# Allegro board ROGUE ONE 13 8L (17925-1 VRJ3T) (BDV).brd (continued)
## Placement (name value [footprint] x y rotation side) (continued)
C7201  SC2D2U10V3KX-1DLGP-U  [C603H36]  18.23 33.55 270 top
C7202  SC2D2U10V3KX-1DLGP-U  [C603H36]  14.92 29.05 180 top
C7203  SC2D2U10V3KX-1DLGP-U  [C603H36]  18.2 37 270 top
C7204  SC22U6D3V3MX-L1-GP  [C603H40]  7.38 32.15 270 top
C7205  SC22U6D3V3MX-1-DL-GP  [C603H40]  7.38 33.42 270 top
C7206  SCD1U16V2KX-3DLGP  [C402H22]  7.38 32.15 90 bottom
C7208  SC10U6D3V3MX-DL-GP  [C603H36]  16.22 29.05 0 top
C7210  SC1U10V2KX-1DLGP  [C402H22]  14.03 36.21 0 bottom
C7211  SC10U6D3V3MX-DL-GP  [C603H36]  18.2 35.73 90 top
C7212  SCD22U10V2KX-2-GP  [C402H22]  11.57 37.74 180 bottom
C7217  SC220P50V2KX-3DLGP  [C402H22]  9.36 42.33 180 top
C7218  SC220P50V2KX-3DLGP  [C402H22]  7.99 42.36 180 top
C7244  SCD1U16V2KX-3DLGP  [C402H22]  16.3 21.61 90 bottom
C7301  SC1U25V3KX-1-DLGP  [C603H36]  6.97 39.36 180 top
C7302  SCD1U25V2KX-1-DL-GP  [C402H22]  7.02 59.84 90 bottom
C7303  SCD1U25V2KX-1-DL-GP  [C402H22]  11.7 60.34 180 top
C7304  SCD1U25V2KX-1-DL-GP  [C402H22]  7.02 60.6 90 bottom
C7305  SC4D7U25V5KX-DL-GP  [C805H54]  10.71 60.19 270 bottom
C7306  SC1U25V3KX-1-DLGP  [C603H36]  9.56 57.68 0 top
C7307  SCD1U25V2KX-1-DL-GP  [C402H22]  10.58 57.55 0 top
C7401  SC1500P50V2KX-2-DL-GP  [C402H22]  20.21 59.33 90 bottom
C9106  SC10U6D3V3MX-DL-GP  [C603H36]  187.49 47.01 90 top
C9108  SCD1U16V2KX-3DLGP  [C402H22]  185.84 45.74 0 top
C9109  SC10U6D3V3MX-DL-GP  [C603H36]  176.57 46.63 270 top
C9112  SCD1U16V2KX-3DLGP  [C402H22]  183.81 52.72 90 top
C9113  SCD1U16V2KX-3DLGP  [C402H22]  177.05 47.87 270 top
C9201  SC1U10V2KX-1DLGP  [C402H22]  181.52 88.16 90 bottom
CN6601  STAR-CON40-8-GP  [300E40-1010RA-G3]  170.3 37.55 180 bottom
CPU1  WHISKEY-LAKE-GP  [BGA1528M2446-1H52]  116.72 76.86 270 bottom
D1701  RB520S30-GP  [SOD523AKH26]  125.52 49.17 90 bottom
D2401  RB751V-40H-GP  [SOD323AKH38]  20.99 23.64 90 bottom
D2402  L1SS355T1G-GP  [SOD323AKH44]  32.2 25.47 90 top
D2403  RB520S30-GP  [SOD523AKH26]  43.68 27.2 270 bottom
D2404  RB751V-40H-GP  [SOD323AKH38]  31.03 12.85 180 top
D2501  BAT54C-12-GP  [SOT-23-9H44]  193.33 40.02 0 bottom
D2502  RB751VM-40TE-17-GP  [SOD323-2513AKH36]  186.86 61.99 270 top
D2503  BAT54A-11-GP  [SOT-23-9H44]  158.28 68.73 270 bottom
D2601  RB551V30-GP  [SOD323AKH38]  187.36 70.12 270 bottom
D2702  BAT54C-12-GP  [SOT-23-9H44]  180.46 11.96 180 bottom
D4001  L1SS355T1G-GP  [SOD323AKH44]  92.7 9.04 270 bottom
D4002  RB520S30-GP  [SOD523AKH26]  17.69 18.43 90 top
D4003  RB520S30-GP  [SOD523AKH26]  14.9 18.56 180 bottom
D4301  P6AF24A-R1-00001-GP  [D4724AKH44]  46.7 92.12 180 bottom
D4302  LBAV99LT1G-1-GP  [SOT23-2D4-312H44]  34.2 31.9 180 top
D4303  L30ESD24VC3-2-GP  [SOT23-2D4-312H60]  47.54 98.7 180 bottom
D4304  SMF18A-GP  [SOD123AK-2H43]  98.72 8.78 270 bottom
D4305  RB751V-40-2-GP  [SOD323AKH38]  19.72 44.85 0 top
D5501  BAT54C-12-GP  [SOT-23-9H44]  77.13 99.33 180 bottom
D5502  BAT54C-12-GP  [SOT-23-9H44]  73.7 99.46 180 bottom
D5701  LBAW56LT1G-GP  [SOT23-2D4-312H44]  21.22 95.37 0 top
D6101  RB520S30-GP  [SOD523AKH26]  168.19 51.71 90 top
D6102  RB520S30-GP  [SOD523AKH26]  167.43 46.88 90 top
D6401  BAT54A-11-GP  [SOT-23-9H44]  175.81 4.97 270 bottom
D7301  BX310F-R1-00000-GP  [D4724AKH44]  12.87 57.8 90 bottom
DB1  DM-ACES-CON14-5-GP-01  [DM-87212-1400N-01]  36.49 21.35 90 top
DB3  ACES-CON6-58-GP  [50696-00601-001]  34.84 2.3 0 top
DCIN1  ETY-CON8-23-GP-U  [3703K-Q08N-03R-U]  39.7 94.3 0 bottom
EC1706  SC1KP50V2KX-1DLGP  [C402H22]  146.42 83.13 180 bottom
EC1707  SCD1U16V2KX-3DLGP  [C402H22]  136.18 48 90 bottom
EC1712  SCD1U16V2KX-3DLGP  [C402H22]  132.25 48.81 270 bottom
EC1801  SC10P50V2JN-4DLGP  [C402H22]  130.49 56.84 90 top
EC1803  SC4D7P50V2BN-2-GP  [C402H22]  125.44 57.52 270 bottom
EC1804  SCD1U16V2KX-3DLGP  [C402H22]  135.8 26.18 0 bottom
EC1901  SC10P50V2JN-4DLGP  [C402H22]  169.84 22.7 270 bottom
EC1903  SC33P50V2JN-3DLGP  [C402H22]  173.67 24.43 0 bottom
EC2201  SCD1U25V2KX-1-DL-GP  [C402H22]  127.22 81.35 270 top
EC2402  SCD1U25V2KX-1-DL-GP  [C402H22]  23.56 17.54 0 top
EC2403  SCD1U25V2KX-1-DL-GP  [C402H22]  43.22 23.51 180 bottom
EC2501  SC4D7P50V2BN-2-GP  [C402H22]  137.63 54.6 180 bottom
EC2502  SC4D7P50V2BN-2-GP  [C402H22]  153.1 55.54 180 bottom
EC2503  SC10P50V2JN-4DLGP  [C402H22]  139.97 56.69 90 bottom
EC2601  SC10P50V2JN-4DLGP  [C402H22]  184.32 68.85 90 bottom
EC2602  SC10P50V2JN-4DLGP  [C402H22]  185.84 68.85 270 bottom
EC2709  SCD01U50V2KX-1DLGP  [C402H22]  183.3 14.88 270 bottom
EC2710  SCD01U50V2KX-1DLGP  [C402H22]  183.25 20.11 270 bottom
EC2711  SCD01U50V2KX-1DLGP  [C402H22]  183.43 24.78 90 top
EC2712  SCD1U25V2KX-1-DL-GP  [C402H22]  183.43 24.78 270 bottom
EC2713  SCD1U25V2KX-1-DL-GP  [C402H22]  177.71 16.78 180 top
EC2714  SCD1U25V2KX-1-DL-GP  [C402H22]  183.3 14.88 90 top
EC2901  SC1KP50V2KX-1DLGP  [C402H22]  13.25 3.7 0 top
EC2902  SC1KP50V2KX-1DLGP  [C402H22]  15.03 4.97 90 top
EC2903  SC1KP50V2KX-1DLGP  [C402H22]  16.68 4.97 270 top
EC2904  SC1KP50V2KX-1DLGP  [C402H22]  18.84 4.34 0 top
EC4301  SC10U25V5KX-DL-GP  [C805H58]  39.76 88.33 90 bottom
EC4302  SCD1U25V2KX-1-DL-GP  [C402H22]  39.79 89.3 270 top
EC4306  SC10P50V2JN-4DLGP  [C402H22]  117.01 18.31 90 top
EC4307  SC1KP50V2KX-1DLGP  [C402H22]  102.27 13.1 0 bottom
EC4308  SCD1U25V2KX-1-DL-GP  [C402H22]  101.77 8.02 180 bottom
EC4309  SC10P50V2JN-4DLGP  [C402H22]  115.1 20.08 90 top
EC4310  SC10P50V2JN-4DLGP  [C402H22]  113.58 20.08 270 top
EC4311  SCD1U25V2KX-1-DL-GP  [C402H22]  46.52 95.4 270 bottom
EC4312  SC1KP50V2KX-1DLGP  [C402H22]  39.79 88.54 270 top
EC4313  SCD1U25V2KX-1-DL-GP  [C402H22]  39.79 87.78 270 top
EC4534  SC2D2U25V5KX-2-GP  [C805H54]  99.15 24.94 0 bottom
EC4701  SCD1U25V2KX-1-DL-GP  [C402H22]  96.05 70.38 90 top
EC5001  SCD1U25V2KX-1-DL-GP  [C402H22]  122.92 74.44 270 top
EC5501  SC8P50V2DN-1DL-GP  [C402H22]  100.12 99.84 90 top
EC5503  SC33P50V2JN-3DLGP  [C402H22]  110.15 101.11 90 top
EC5504  SC33P50V2JN-3DLGP  [C402H22]  108.62 101.11 270 top
EC5505  SCD1U25V2KX-1-DL-GP  [C402H22]  144.95 100.86 180 top
EC5506  SC33P50V2JN-3DLGP  [C402H22]  121.07 98.44 270 top
EC6501  SC33P50V2JN-3DLGP  [C402H22]  89.96 10.56 90 top
EC6502  SC33P50V2JN-3DLGP  [C402H22]  88.43 10.56 270 top
EC6503  SC33P50V2JN-3DLGP  [C402H22]  89.68 12.11 0 bottom
EC6504  SC33P50V2JN-3DLGP  [C402H22]  84.72 13.07 90 bottom
EC8901  SCD1U25V2KX-1-DL-GP  [C402H22]  125.26 97.3 180 top
EC8902  SCD1U25V2KX-1-DL-GP  [C402H22]  77.64 92.47 180 top
EC8903  SCD1U25V2KX-1-DL-GP  [C402H22]  96.91 96.87 270 top
EC8904  SCD1U25V2KX-1-DL-GP  [C402H22]  105.02 97.45 180 top
EC8905  SC1U10V2KX-1DLGP  [C402H22]  99.48 84.09 180 top
EC8906  SCD1U25V2KX-1-DL-GP  [C402H22]  103.04 80.54 0 top
EC8907  SCD1U25V2KX-1-DL-GP  [C402H22]  143.8 98.44 180 top
EC8908  SCD1U25V2KX-1-DL-GP  [C402H22]  52.11 66.19 270 top
EC8909  SCD1U25V2KX-1-DL-GP  [C402H22]  55.92 84.85 270 top
EC8910  SCD1U25V2KX-1-DL-GP  [C402H22]  39.54 35.83 270 top
EC8911  SCD1U25V2KX-1-DL-GP  [C402H22]  50.59 23.13 0 top
EC8912  SCD1U25V2KX-1-DL-GP  [C402H22]  71.13 22.34 0 top
EC8913  SCD1U25V2KX-1-DL-GP  [C402H22]  61.76 64.15 90 top
EC8914  SCD1U25V2KX-1-DL-GP  [C402H22]  107.23 25.16 0 top
EC8915  SCD1U25V2KX-1-DL-GP  [C402H22]  153.33 27.96 180 top
EC8916  SCD1U25V2KX-1-DL-GP  [C402H22]  164 36.98 270 top
EC8917  SCD1U25V2KX-1-DL-GP  [C402H22]  55.79 80.41 270 top
EC8918  SCD1U25V2KX-1-DL-GP  [C402H22]  171.62 98.87 180 top
EC8919  SCD1U25V2KX-1-DL-GP  [C402H22]  168.42 43.93 180 top
EC8920  SCD1U25V2KX-1-DL-GP  [C402H22]  124.98 4.67 0 top
EC8921  SCD1U25V2KX-1-DL-GP  [C402H22]  176.82 68.52 180 top
EC8922  SCD1U25V2KX-1-DL-GP  [C402H22]  79.67 8.27 180 top
EC8923  SCD1U25V2KX-1-DL-GP  [C402H22]  124.83 11.52 180 top
EC8924  SCD1U25V2KX-1-DL-GP  [C402H22]  116.24 23.51 90 top
EC8925  SCD1U25V2KX-1-DL-GP  [C402H22]  75.22 13.73 90 top
EC8926  SCD1U25V2KX-1-DL-GP  [C402H22]  174.18 2.1 270 bottom
EC8927  SCD1U25V2KX-1-DL-GP  [C402H22]  7.71 4.41 0 top
EC8928  SCD1U25V2KX-1-DL-GP  [C402H22]  5.25 31.39 180 top
EC8929  SCD1U25V2KX-1-DL-GP  [C402H22]  66.08 12.08 270 top
EC8930  SCD1U25V2KX-1-DL-GP  [C402H22]  65.67 50.23 270 top
EC8931  SCD1U25V2KX-1-DL-GP  [C402H22]  113.96 52.34 270 top
EC8932  SCD1U25V2KX-1-DL-GP  [C402H22]  113.96 56.41 270 top
EC8933  SCD1U25V2KX-1-DL-GP  [C402H22]  124.12 51.07 90 top
EC8934  SCD1U25V2KX-1-DL-GP  [C402H22]  123.23 54.93 90 top
EC8937  SCD1U25V2KX-1-DL-GP  [C402H22]  75.91 77.23 0 top
EC8938  SCD1U25V2KX-1-DL-GP  [C402H22]  73.19 88.66 270 top
EC8939  SCD1U25V2KX-1-DL-GP  [C402H22]  66.82 52.9 180 top
EC8940  SCD1U25V2KX-1-DL-GP  [C402H22]  89.55 49.45 180 top
EC8941  SCD1U25V2KX-1-DL-GP  [C402H22]  86.96 52.39 180 top
EC8942  SCD1U25V2KX-1-DL-GP  [C402H22]  112.82 48.91 270 top
EC8943  SCD1U25V2KX-1-DL-GP  [C402H22]  166.54 70.25 90 top
EC8944  SCD1U25V2KX-1-DL-GP  [C402H22]  168.44 103.9 270 top
EC8945  SCD1U25V2KX-1-DL-GP  [C402H22]  56.3 89.68 270 top
EC8946  SCD1U25V2KX-1-DL-GP  [C402H22]  79.8 24.53 180 bottom
EC8947  SCD1U25V2KX-1-DL-GP  [C402H22]  45.91 53.99 0 bottom
EC8948  SCD1U25V2KX-1-DL-GP  [C402H22]  47.79 38.37 270 bottom
EC8949  SCD1U25V2KX-1-DL-GP  [C402H22]  62.78 25.09 180 bottom
EC8950  SCD1U25V2KX-1-DL-GP  [C402H22]  58.36 24.99 180 bottom
ED301  AZ5125-02S-R7G-GP  [SOT23-2D4-312H46]  117.21 95.24 180 bottom
ED1701  AZ5125-02S-R7G-GP  [SOT23-2D4-312H46]  139.71 54.76 90 top
ED1702  AZ5125-02S-R7G-GP  [SOT23-2D4-312H46]  156.99 87.67 0 top
ED1703  AZ5125-02S-R7G-GP  [SOT23-2D4-312H46]  16.55 14.83 180 bottom
ED1704  AZ5125-02S-R7G-GP  [SOT23-2D4-312H46]  56.22 78.83 90 bottom
ED1801  AZ5125-02S-R7G-GP  [SOT23-2D4-312H46]  138.65 47.82 0 bottom
ED2403  AZ5125-02S-R7G-GP  [SOT23-2D4-312H46]  24.68 38.5 90 bottom
ED4304  LBAV99LT1G-1-GP  [SOT23-2D4-312H44]  36.49 34.44 0 bottom
ED4305  LBAV99LT1G-1-GP  [SOT23-2D4-312H44]  26.84 31.01 0 top
ED4306  LBAV99LT1G-1-GP  [SOT23-2D4-312H44]  30.27 30.37 0 top
ED5501  AZC099-04S-2-GP  [SOT-6H58]  116.88 99.03 180 bottom
ED5502  AZ5125-02S-R7G-GP  [SOT23-2D4-312H46]  136.54 99.15 270 bottom
ED5701  AZ1043-04F-R7G-GP  [DFN10G2510H22]  15.15 84.73 270 top
ED5702  AZ1043-04F-R7G-GP  [DFN10G2510H22]  15.15 88.16 90 top
ED5703  AZ1043-04F-R7G-GP  [DFN10G2510H22]  15.15 91.2 270 top
ED6301  L05ESDL5V0NA-4-GP  [SLP2510P8-1H22]  185.38 11.68 90 bottom
ED6302  L05ESDL5V0NA-4-GP  [SLP2510P8-1H22]  153.61 14.37 270 top
ED6401  AZ5125-02S-R7G-GP  [SOT23-2D4-312H46]  17.44 100.22 90 top
ED7301  L05ESDL5V0NA-4-GP  [SLP2510P8-1H22]  13.7 70.12 90 top
ED7302  L05ESDL5V0NA-4-GP  [SLP2510P8-1H22]  13.88 66.95 90 top
ED7303  L05ESDL5V0NA-4-GP  [SLP2510P8-1H22]  12.1 65.96 180 bottom
ED7305  AZ5315-02F-GP  [SOT883-1D0-321H20]  14.95 63.54 0 bottom
ED7306  AZ5315-02F-GP  [SOT883-1D0-321H20]  10.58 71.39 180 bottom
ED9202  AZ5315-02F-GP  [SOT883-1D0-321H20]  181.57 85.26 0 bottom
EL4301  0R0805-PAD-2-GP-U  [0R0805-PAD-1-U]  44.24 87.8 180 bottom
EL4302  0R0805-PAD-2-GP-U  [0R0805-PAD-1-U]  42.33 87.8 180 bottom
EL4303  0R0805-PAD-2-GP-U  [0R0805-PAD-1-U]  35.98 88.33 90 bottom
EL4304  0R0805-PAD-2-GP-U  [0R0805-PAD-1-U]  35.98 86.51 90 bottom
EL5501  DLM0NSN900HY2D-GP  [LD85D65-4P-1H20]  117.9 102 180 bottom
EL7201  DLM0NSN900HY2D-GP  [LD85D65-4P-1H20]  12.87 64.05 0 bottom
EL7202  DLM0NSN900HY2D-GP  [LD85D65-4P-1H20]  11.32 64.05 0 bottom
ER2901  0R0603-PAD-2-GP-U  [0R0603-PAD-1-U]  16.68 6.75 0 top
ER2902  0R0603-PAD-2-GP-U  [0R0603-PAD-1-U]  18.2 6.75 0 top
ER2903  0R0603-PAD-2-GP-U  [0R0603-PAD-1-U]  13.25 5.73 0 top
ER2904  0R0603-PAD-2-GP-U  [0R0603-PAD-1-U]  15.41 6.75 0 top
ER7301  0R5J-5-GP  [R805H24]  7.15 57.68 0 bottom
ER7302  0R5J-5-GP  [R805H24]  9.06 57.68 0 bottom
F5501  POLYSW-1D1A6V-9-GP-U  [POLYSW-2114H30]  137.3 100.65 0 top
F5502  POLYSW-1D1A6V-9-GP-U  [POLYSW-2114H30]  104.81 101.24 270 top
F5503  POLYSW-1D1A24V-GP-U  [POLYSW-4633-UH43]  75.73 95.65 90 bottom
F5504  POLYSW-1D1A6V-9-GP-U  [POLYSW-2114H30]  122.09 101.62 0 top
F5701  POLYSW-1D1A6V-9-GP-U  [POLYSW-2114H30]  17.82 95.14 270 top
F6501  POLYSW-1D1A6V-9-GP-U  [POLYSW-2114H30]  72.05 16.4 180 bottom
FAN1  ACES-CON4-29-GP  [50224-0040N-001]  186.8 76.6 270 bottom
FC1102  SC2D2U6D3V2MX-DL-GP  [C402H22]  123.23 54.12 90 top
FC1103  SC18P50V2JN-1DLGP  [C402H22]  113.58 69.49 180 top
FC1801  SC4D7P50V2BN-2-GP  [C402H22]  125.44 56.74 270 bottom
FC2738  SC12P50V2JN-DL-GP  [C402H22]  167.6 18.48 270 bottom
FC5501  SC18P50V2JN-1DLGP  [C402H22]  100.5 97.17 270 top
FC5502  SC18P50V2JN-1DLGP  [C402H22]  104.56 98.57 90 top
FC5505  SC18P50V2JN-1DLGP  [C402H22]  80.05 104.29 90 bottom
FC5701  SC12P50V2JN-DL-GP  [C402H22]  34.08 87.57 0 bottom
FC5702  SC12P50V2JN-DL-GP  [C402H22]  31.81 75.13 90 bottom
FC5703  SC12P50V2JN-DL-GP  [C402H22]  26.28 75.84 180 bottom
FC5704  SC12P50V2JN-DL-GP  [C402H22]  24.3 77.34 180 bottom
FC6101  SC10P50V2JN-4DLGP  [C402H22]  166.54 63.39 0 top
FC8905  SC4D7P50V2BN-2-GP  [C402H22]  154.09 27.96 180 top
FC8906  SC4D7P50V2BN-2-GP  [C402H22]  164 37.74 270 top
FC8907  SC4D7P50V2BN-2-GP  [C402H22]  166.16 60.98 90 top
FC8908  SC4D7P50V2BN-2-GP  [C402H22]  166.28 75.46 90 top
FC8909  SC4D7P50V2BN-2-GP  [C402H22]  174.66 97.94 270 top
FC8910  SC4D7P50V2BN-2-GP  [C402H22]  41.75 49.19 270 top
FC8911  SC18P50V2JN-1DLGP  [C402H22]  47.79 39.13 270 bottom
FC8912  SC4D7P50V2BN-2-GP  [C402H22]  100.5 24.4 0 bottom
FC8913  SC18P50V2JN-1DLGP  [C402H22]  170.98 104.41 0 bottom
FC8914  SC4D7P50V2BN-2-GP  [C402H22]  58.71 93.62 180 top
FC8915  SC4D7P50V2BN-2-GP  [C402H22]  61 79.39 90 top
FC8916  SC4D7P50V2BN-2-GP  [C402H22]  62.4 67.28 90 top
FC8917  SC4D7P50V2BN-2-GP  [C402H22]  49.82 63.9 270 top
FC8918  SC4D7P50V2BN-2-GP  [C402H22]  52.36 59.45 90 top
FC8919  SC4D7P50V2BN-2-GP  [C402H22]  43.6 37.1 90 top
FC8920  SC4D7P50V2BN-2-GP  [C402H22]  45.38 28.85 180 top
FC8921  SC4D7P50V2BN-2-GP  [C402H22]  54.14 22.88 0 top
FC8922  SC4D7P50V2BN-2-GP  [C402H22]  72.94 22.88 0 top
FC8923  SC4D7P50V2BN-2-GP  [C402H22]  92.11 22.17 0 top
FC8924  SC4D7P50V2BN-2-GP  [C402H22]  117.26 25.04 0 top
FC8925  SC4D7P50V2BN-2-GP  [C402H22]  6.39 31.13 270 top
FC8926  SC4D7P50V2BN-2-GP  [C402H22]  64.94 3.07 270 top
FC8927  SC4D7P50V2BN-2-GP  [C402H22]  66.82 19.42 270 top
FC8928  SC4D7P50V2BN-2-GP  [C402H22]  125.74 4.67 0 top
FC8929  SC4D7P50V2BN-2-GP  [C402H22]  8.68 15 90 bottom
FC8930  SC4D7P50V2BN-2-GP  [C402H22]  34.35 76.88 270 bottom
FC8931  SC4D7P50V2BN-2-GP  [C402H22]  10.07 13.86 180 bottom
FC8932  SC18P50V2JN-1DLGP  [C402H22]  57.32 89.17 0 bottom
FC8933  SC4D7P50V2BN-2-GP  [C402H22]  154.85 69.87 270 bottom
FC8934  SC18P50V2JN-1DLGP  [C402H22]  170.3 99.21 90 bottom
FC8935  SC4D7P50V2BN-2-GP  [C402H22]  73.57 20.97 180 top
FC8936  SC4D7P50V2BN-2-GP  [C402H22]  80.68 7.64 180 top
FC8937  SC4D7P50V2BN-2-GP  [C402H22]  116.24 22.75 90 top
FC8938  SC4D7P50V2BN-2-GP  [C402H22]  125.59 11.52 180 top
FC8939  SC4D7P50V2BN-2-GP  [C402H22]  115.99 21.99 90 top
FC8940  SC4D7P50V2BN-2-GP  [C402H22]  48.93 61.74 90 bottom
FC8941  SC4D7P50V2BN-2-GP  [C402H22]  38.34 10.84 90 top
FC8942  SC4D7P50V2BN-2-GP  [C402H22]  134.41 5.83 90 top
FC8943  SC18P50V2JN-1DLGP  [C402H22]  145.91 71.49 270 bottom
FC8944  SC4D7P50V2BN-2-GP  [C402H22]  17.26 29.15 0 top
FC8945  SC18P50V2JN-1DLGP  [C402H22]  158.03 94.38 0 bottom
FC8946  SC18P50V2JN-1DLGP  [C402H22]  65.83 46.5 0 bottom
FC8947  SC4D7P50V2BN-2-GP  [C402H22]  72.3 46.5 0 bottom
FC8948  SC18P50V2JN-1DLGP  [C402H22]  113.45 46.37 0 bottom
FC8949  SC18P50V2JN-1DLGP  [C402H22]  142.91 46.5 0 bottom
FC8950  SC4D7P50V2BN-2-GP  [C402H22]  102.78 32.28 180 bottom
FC8951  SC18P50V2JN-1DLGP  [C402H22]  55.28 28.21 180 bottom
FC8952  SC18P50V2JN-1DLGP  [C402H22]  90.59 28.09 180 bottom
FC8953  SC18P50V2JN-1DLGP  [C402H22]  108.5 28.47 180 bottom
FC8954  SC18P50V2JN-1DLGP  [C402H22]  136.06 28.47 180 bottom
FP1  PTWO-CON8-11-GP  [FH52-8S-D5SH]  185.9 85 270 bottom
FSW1  SW-SLIDE3P-11-GP  [MSS3-Q-T-R]  193.46 29.86 90 top
G1801  GAP-OPEN  [CON2O-U]  145.84 25.42 90 bottom
G5701  GAP-CLOSE-PWR-3-GP  [GAP-CLOSE-PWR-3]  35.24 79.88 90 bottom
H1  HOLE335R178-GP  [HOLE335R178]  28.2 99.1 0 bottom
H2  HOLE335R178-GP  [HOLE335R178]  27.2 4.75 0 bottom
H3  HOLE296R182-GP  [HOLE296R182]  182.05 4 0 bottom
H4  HOLE394X394R174-GP  [HOLE394X394R174]  31.2 66.3 0 bottom
H5  HOLE296R182-GP  [HOLE296R182]  150.2 102.46 0 bottom
H6  HOLE276R150-GP  [HOLE276R150]  84.49 89.96 180 bottom
H7  HOLE276R150-GP  [HOLE276R150]  84.49 65.66 180 bottom
H8  HOLE276R150-GP  [HOLE276R150]  145.49 65.66 180 bottom
H9  HOLE276R150-GP  [HOLE276R150]  145.49 89.96 180 bottom
H10  HOLE335R178-GP  [HOLE335R178]  151.2 45.3 0 bottom
H12  STF237R113H62-10-GP  [STF237R113H62]  13.7 76.3 0 bottom
H13  HOLE315R197-GP  [HOLE315R197]  132.42 12.9 0 bottom
HDMI1  SKT-HDMI23-169-GP  [SKT-HDMI23-188142]  3.72 88.52 90 bottom
KB1  ACES-CON30-28-GP  [196528-30041-3]  47.7 8.6 180 bottom
KBBL1  ACES-CON4-90-GP-U  [50698-00401-W01-U]  69.7 6.3 180 bottom
LCD1  STAR-CON50-2-GP-U  [300E50-1030RA-G4]  98.4 99.8 0 bottom
LED1  LED-YW-5-GP  [LED3020-3P-19H44]  3 100.95 0 top
NOREF  -  []  94.41 66.65 90 top
NOREF#2  -  []  142.31 135 0 top
NOREF#3  -  []  7.12 66.59 90 top
NOREF#4  -  []  132.42 19.25 0 top
NOREF#5  -  []  7.12 73.79 0 top
NOREF#6  -  []  6.57 67.39 0 top
NOREF#7  -  [unnamed#2]  197.36 62.3 0 top
NOREF#8  -  []  7.12 73.79 0 top
NOREF#9  -  []  6.57 69.79 0 top
NOREF#10  -  []  108.52 65.55 90 top
NOREF#11  -  []  34.44 100.24 90 top
NOREF#12  -  []  7.78 72.94 90 top
NOREF#13  -  []  142.31 96.9 90 top
NOREF#14  -  [unnamed#2]  178.7 103.35 0 top
NOREF#15  -  []  7.12 73.79 0 top
NOREF#16  -  []  190.85 31.86 90 top
NOREF#17  -  []  7.12 73.79 90 top
NOREF#18  -  []  97.67 63.86 0 top
NOREF#19  -  []  7.12 73.79 0 top
NOREF#20  -  []  163.86 91.95 90 top
NOREF#21  *  [unnamed#2]  11.21 99.19 0 top
NOREF#22  -  []  147.76 140.45 0 top
NOREF#23  -  []  190.57 38.93 0 top
NOREF#24  -  []  5.77 72.59 0 top
NOREF#25  -  []  2.02 64.39 90 top
NOREF#26  -  []  1.05 75.35 0 top
NOREF#27  -  []  -6.23 51.29 0 top
NOREF#28  -  []  7.12 73.79 0 top
NOREF#29  -  []  7.12 73.79 0 top
NOREF#30  -  []  7.12 73.79 90 top
NOREF#31  -  []  163.86 91.45 90 top
NOREF#32  -  []  63.58 195.45 180 top
NOREF#33  -  []  -2.42 85.79 0 top
NOREF#34  -  [unnamed#2]  -1.36 152.4 0 top
NOREF#35  -  []  7.12 73.79 0 top
NOREF#36  -  []  7.12 73.79 90 top
NOREF#37  -  []  7.12 73.79 0 top
NOREF#38  -  []  5.77 67.79 0 top
NOREF#39  -  []  5.77 68.59 0 top
NOREF#40  -  []  6.57 72.99 0 top
NOREF#41  -  [unnamed#2]  198.25 159.56 0 top
NOREF#42  -  []  190.85 31.86 90 top
NOREF#43  -  []  7.12 73.79 0 top
NOREF#44  -  []  6.57 71.54 0 top
NOREF#45  *  [unnamed#2]  -1.25 16.64 0 top
NOREF#46  -  []  7.12 73.79 0 top
NOREF#47  *  [unnamed#2]  197.18 202.85 0 top
NOREF#48  -  []  6.25 74.99 0 top
NOREF#49  -  []  202.22 79.65 90 top
NOREF#50  -  []  34.44 110.05 0 top
NOREF#51  -  [unnamed#2]  -2.25 55.14 0 top
NOREF#52  *  [unnamed#2]  5.55 7.32 0 top
NOREF#53  -  []  7.12 73.79 0 top
NOREF#54  -  []  39.7 94.3 90 top
NOREF#55  -  []  -6.21 135.1 270 top
NOREF#56  -  []  6.57 72.99 90 top
NOREF#57  -  []  34.18 107.32 0 top
NOREF#58  -  []  35.76 110.86 0 top
NOREF#59  -  []  141.77 141 0 top
NOREF#60  -  []  -14.58 62.72 90 top
NOREF#61  -  []  -0.85 -17 0 top
NOREF#62  -  []  94.41 66 0 top
NOREF#63  *  [unnamed#2]  186.39 102.82 0 top
NOREF#64  -  []  -6.23 0 0 top
NOREF#65  -  []  43.2 90.53 90 top
NOREF#66  -  []  190.85 41.66 0 top
NOREF#67  -  []  5.77 71.79 0 top
NOREF#68  -  []  7.12 73.79 0 top
NOREF#69  -  []  7.12 73.79 0 top
NOREF#70  -  []  5.77 69.39 0 top
NOREF#71  -  [unnamed#2]  -2.88 21.99 0 top
NOREF#72  *  [unnamed#2]  197.51 35.75 0 top
NOREF#73  -  []  59.48 102.63 0 top
NOREF#74  -  []  6.57 68.84 0 top
NOREF#75  -  []  173.5 85.59 0 top
NOREF#76  -  []  -3.43 80.64 0 top
NOREF#77  -  [unnamed#2]  -2.19 166.24 0 top
NOREF#78  -  []  93.72 64.86 0 top
NOREF#79  -  []  5.77 72.59 90 top
NOREF#80  -  []  192.17 42.47 0 top
NOREF#81  -  [unnamed#2]  198.83 48.72 0 top
NOREF#82  -  []  195.34 31.86 90 top
NOREF#83  -  []  141.77 90.91 90 top
NOREF#84  -  []  6.57 70.59 0 top
NOREF#85  -  []  6.25 65.39 0 top
NOREF#86  -  []  141.9 12.46 0 top
NOREF#87  -  [unnamed#2]  2.4 3.35 0 top
NOREF#88  *  [unnamed#2]  188 3.32 0 top
NOREF#89  -  []  -1.99 75.35 0 top
NOREF#90  *  [unnamed#2]  185.89 28.53 0 top
NOREF#91  -  []  -4.28 96.54 90 top
NOREF#92  -  []  2.02 75.99 0 top
NOREF#93  -  []  2.02 64.39 0 top
NOREF#94  -  []  5.77 70.99 0 top
NOREF#95  -  []  8.32 75.35 90 top
NOREF#96  -  []  -73.37 -35.67 0 top
NOREF#97  -  []  34.44 100.24 90 top
NOREF#98  -  []  -0.85 -17 0 top
NOREF#99  -  [unnamed#2]  198.55 192.96 0 top
NOREF#100  -  []  -0.85 -17 0 top
NOREF#101  *  [unnamed#2]  5.55 7.32 180 bottom
NOREF#102  *  [unnamed#2]  197.51 35.75 180 bottom
NOREF#103  *  [unnamed#2]  -1.25 16.64 180 bottom
NOREF#104  -  []  101 50.95 180 bottom
NOREF#105  -  []  59.48 102.63 180 bottom
NOREF#106  -  []  7.53 44.72 180 bottom
NOREF#107  -  []  -1.74 118.38 180 bottom
NOREF#108  -  []  196.51 54.37 180 bottom
NOREF#109  *  [unnamed#2]  186.39 102.82 180 bottom
NOREF#110  -  []  164.91 29.1 180 bottom
NOREF#111  *  [unnamed#2]  151.93 3.83 180 bottom
NOREF#112  *  [unnamed#2]  11.21 99.19 180 bottom
NOREF#113  *  [unnamed#2]  197.18 202.85 180 bottom
NOREF#114  -  []  -4.28 111.02 270 bottom
NOREF#115  -  []  197.78 96.54 180 bottom
NOREF#116  *  [unnamed#2]  185.89 28.53 180 bottom
NOREF#117  *  [unnamed#2]  154.47 86.38 180 bottom
NOREF#118  *  [unnamed#2]  88.69 59.45 180 bottom
NOREF#119  -  []  -1.23 160.42 180 bottom
PC1001  SC22U6D3V3MX-1-DL-GP  [C603H40]  86.53 57.04 0 top
PC1002  SC22U6D3V3MX-1-DL-GP  [C603H40]  76.62 91.97 180 top
PC1003  SC22U6D3V3MX-1-DL-GP  [C603H40]  92.75 85.62 0 top
PC1004  SC22U6D3V3MX-1-DL-GP  [C603H40]  113.65 79.7 90 top
PC1005  SC22U6D3V3MX-1-DL-GP  [C603H40]  108.88 76.09 270 top
PC1006  SC22U6D3V3MX-1-DL-GP  [C603H40]  78.14 93.87 270 top
PC1007  SC22U6D3V3MX-1-DL-GP  [C603H40]  117.11 79.77 270 top
PC1008  SC22U6D3V3MX-1-DL-GP  [C603H40]  117.11 75.96 270 top
PC1009  SC22U6D3V3MX-1-DL-GP  [C603H40]  116.88 97.17 90 top
PC1010  SC22U6D3V3MX-1-DL-GP  [C603H40]  120.44 77.82 90 top
PC1011  SC22U6D3V3MX-1-DL-GP  [C603H40]  118.45 72.18 0 top
PC1012  SC22U6D3V3MX-1-DL-GP  [C603H40]  119.72 72.18 0 top
PC1013  SC22U6D3V3MX-1-DL-GP  [C603H40]  120.99 72.18 0 top
PC1014  SC22U6D3V3MX-1-DL-GP  [C603H40]  117.18 72.18 0 top
PC1015  SC22U6D3V3MX-1-DL-GP  [C603H40]  117.11 81.04 270 top
PC1016  SC22U6D3V3MX-1-DL-GP  [C603H40]  119.85 82.95 90 top
PC1017  SC22U6D3V3MX-1-DL-GP  [C603H40]  115.36 72.15 0 top
PC1018  SC22U6D3V3MX-1-DL-GP  [C603H40]  113.17 97.66 180 top
PC1019  SC22U6D3V3MX-1-DL-GP  [C603H40]  114.44 97.66 180 top
PC1020  SC22U6D3V3MX-1-DL-GP  [C603H40]  120.44 80.36 90 top
PC1021  SC22U6D3V3MX-1-DL-GP  [C603H40]  113.65 80.97 90 top
PC1022  SC22U6D3V3MX-1-DL-GP  [C603H40]  73.19 81.68 270 top
PC1023  SC22U6D3V3MX-1-DL-GP  [C603H40]  79.54 84.75 270 bottom
PC1024  SC22U6D3V3MX-1-DL-GP  [C603H40]  117.11 77.23 270 top
PC1025  SC22U6D3V3MX-1-DL-GP  [C603H40]  117.11 78.5 270 top
PC1026  SC22U6D3V3MX-1-DL-GP  [C603H40]  79.54 82.21 270 bottom
PC1027  SC22U6D3V3MX-1-DL-GP  [C603H40]  94.53 85.74 0 top
PC1028  SC22U6D3V3MX-1-DL-GP  [C603H40]  113.65 78.43 90 top
PC1029  SC22U6D3V3MX-1-DL-GP  [C603H40]  74.87 77.28 0 top
PC1030  SC22U6D3V3MX-1-DL-GP  [C603H40]  108.88 77.36 270 top
PC1031  SC22U6D3V3MX-1-DL-GP  [C603H40]  113.65 74.62 90 top
PC1032  SC22U6D3V3MX-1-DL-GP  [C603H40]  113.65 77.16 90 top
PC1034  SC22U6D3V3MX-1-DL-GP  [C603H40]  79.54 83.48 270 bottom
PC1036  SC22U6D3V3MX-1-DL-GP  [C603H40]  73.19 84.22 270 top
PC1037  SC22U6D3V3MX-1-DL-GP  [C603H40]  89.07 57.04 0 top
PC1038  SC22U6D3V3MX-1-DL-GP  [C603H40]  104.69 82.95 90 top
PC1039  SC22U6D3V3MX-1-DL-GP  [C603H40]  85.26 57.04 0 top
PC1040  SC22U6D3V3MX-1-DL-GP  [C603H40]  95.54 69.36 90 top
PC1041  SC22U6D3V3MX-1-DL-GP  [C603H40]  100.88 81.04 90 top
PC1042  SC22U6D3V3MX-1-DL-GP  [C603H40]  104.31 74.82 270 top
PC1043  SC22U6D3V3MX-1-DL-GP  [C603H40]  91.48 83.08 180 top
PC1044  SC22U6D3V3MX-1-DL-GP  [C603H40]  104.23 73.55 270 top
PC1045  SC22U6D3V3MX-1-DL-GP  [C603H40]  90.34 57.04 0 top
PC1046  SC22U6D3V3MX-1-DL-GP  [C603H40]  104.31 76.09 270 top
PC1047  SC22U6D3V3MX-1-DL-GP  [C603H40]  88.2 76.62 0 top
PC1048  SC22U6D3V3MX-1-DL-GP  [C603H40]  100.88 79.77 90 top
PC1049  SC22U6D3V3MX-1-DL-GP  [C603H40]  95.8 84.09 180 top
PC1050  SC22U6D3V3MX-1-DL-GP  [C603H40]  100.88 73.42 90 top
PC1051  SC22U6D3V3MX-1-DL-GP  [C603H40]  83.35 57.04 0 top
PC1052  SC22U6D3V3MX-1-DL-GP  [C603H40]  94.02 83.08 180 top
PC1053  SC22U6D3V3MX-1-DL-GP  [C603H40]  90.21 83.08 180 top
PC1054  SC22U6D3V3MX-1-DL-GP  [C603H40]  100.57 83.74 180 top
PC1055  SC22U6D3V3MX-1-DL-GP  [C603H40]  88.94 83.08 180 top
PC1056  SC22U6D3V3MX-1-DL-GP  [C603H40]  93.77 73.93 180 top
PC1057  SC22U6D3V3MX-1-DL-GP  [C603H40]  80.81 57.04 0 top
PC1058  SC22U6D3V3MX-1-DL-GP  [C603H40]  100.88 74.69 90 top
PC1059  SC22U6D3V3MX-1-DL-GP  [C603H40]  92.75 83.08 180 top
PC1060  SC22U6D3V3MX-1-DL-GP  [C603H40]  96.56 71.39 90 top
PC1061  SC22U6D3V3MX-1-DL-GP  [C603H40]  100.88 75.96 90 top
PC1062  SC22U6D3V3MX-1-DL-GP  [C603H40]  100.88 77.23 90 top
PC1063  SC22U6D3V3MX-1-DL-GP  [C603H40]  89.47 76.62 0 top
PC1064  SC22U6D3V3MX-1-DL-GP  [C603H40]  76.37 73.81 270 top
PC1065  SC22U6D3V3MX-1-DL-GP  [C603H40]  79.54 57.04 0 top
PC1066  SC22U6D3V3MX-1-DL-GP  [C603H40]  100.88 78.5 90 top
PC1067  SC22U6D3V3MX-1-DL-GP  [C603H40]  104.31 77.36 270 top
PC1068  SC22U6D3V3MX-1-DL-GP  [C603H40]  76.75 75.84 270 top
PC1069  SC22U6D3V3MX-1-DL-GP  [C603H40]  87.8 57.04 0 top
PC1070  SC22U6D3V3MX-1-DL-GP  [C603H40]  82.08 57.04 0 top
PC1071  SC22U6D3V3MX-1-DL-GP  [C603H40]  123.31 75.46 270 top
PC1072  SC22U6D3V3MX-1-DL-GP  [C603H40]  128.18 83.33 90 top
PC1073  SC22U6D3V3MX-1-DL-GP  [C603H40]  122.21 82.19 270 top
PC1074  SC22U6D3V3MX-1-DL-GP  [C603H40]  139.49 97.68 180 top
PC1075  SC22U6D3V3MX-1-DL-GP  [C603H40]  123.31 76.73 270 top
PC1076  SC22U6D3V3MX-1-DL-GP  [C603H40]  124.25 80.66 90 top
PC1077  SC22U6D3V3MX-1-DL-GP  [C603H40]  124.25 79.39 90 top
PC1078  SC22U6D3V3MX-1-DL-GP  [C603H40]  138.09 97.68 180 top
PC1079  SC22U6D3V3MX-1-DL-GP  [C603H40]  73.19 82.95 270 top
PC1080  SC22U6D3V3MX-1-DL-GP  [C603H40]  113.65 75.89 90 top
PC1081  SC22U6D3V3MX-1-DL-GP  [C603H40]  117.11 74.69 270 top
PC1082  SC22U6D3V3MX-1-DL-GP  [C603H40]  120.44 76.55 90 top
PC1083  SC22U6D3V3MX-1-DL-GP  [C603H40]  120.44 79.09 90 top
PC1084  SC22U6D3V3MX-1-DL-GP  [C603H40]  120.44 75.28 90 top
PC4401  SC10U25V5KX-DL-GP  [C805H58]  39.41 62.25 90 bottom
PC4402  SC10U25V5KX-DL-GP  [C805H58]  39.66 58.31 90 bottom
PC4403  SC10U25V5KX-DL-GP  [C805H58]  44.74 58.31 270 bottom
PC4404  SC10U25V5KX-DL-GP  [C805H58]  39.66 56.41 90 bottom
PC4405  SC10U25V5KX-DL-GP  [C805H58]  44.74 56.41 270 bottom
PC4406  SCD1U25V2KX-1-DL-GP  [C402H22]  44.36 39.39 90 top
PC4407  SC10U25V5KX-DL-GP  [C805H58]  47.92 49.17 270 bottom
PC4408  SC10U25V5KX-DL-GP  [C805H58]  47.92 47.26 270 bottom
PC4409  SC10U25V5KX-DL-GP  [C805H58]  97.96 19.96 90 bottom
PC4410  SC10U25V5KX-DL-GP  [C805H58]  47.92 51.07 270 bottom
PC4411  SC10U25V5KX-DL-GP  [C805H58]  40.17 39.9 180 bottom
PC4412  SC10U25V5KX-DL-GP  [C805H58]  42.08 39.9 180 bottom
PC4413  SC10U25V5KX-DL-GP  [C805H58]  102.15 21.99 270 bottom
PC4414  SC10U25V5KX-DL-GP  [C805H58]  102.15 20.08 270 bottom
PC4415  SC4D7U6D3V3KX-DLGP  [C603H36]  26.58 50.44 270 top
PC4416  SC1U25V3KX-1-DLGP  [C603H36]  25.16 52.7 0 top
PC4417  SC1U25V3KX-1-DLGP  [C603H36]  27.98 52.34 0 top
PC4418  SC22U25V5MX-GP  [C805H58]  43.98 39.9 180 bottom
PC4419  SC1U25V3KX-1-DLGP  [C603H36]  23.86 51.22 180 top
PC4420  SCD022U16V2KX-3DLGP  [C402H22]  26.46 48.28 90 bottom
PC4421  SC4D7U6D3V3KX-DLGP  [C603H36]  33.29 49.98 90 top
PC4422  SC4D7U6D3V3KX-DLGP  [C603H36]  21.65 49.27 270 top
PC4423  SCD22U25V3KX-DL-GP  [C603H36]  33.29 48.71 270 top
PC4424  SC1U50V3KX-1-GP  [C603H36]  34.18 43.05 180 top
PC4425  SC1U25V3KX-1-DLGP  [C603H36]  32.35 43.96 270 top
PC4426  SC1U50V3KX-1-GP  [C603H36]  30.52 42.56 180 top
PC4427  SC10U25V5KX-DL-GP  [C805H58]  97.7 14.88 90 bottom
PC4428  SC10U25V5KX-DL-GP  [C805H58]  101.64 14.88 270 bottom
PC4429  SC4700P25V2KX-4-GP  [C402H22]  29.76 45.36 0 bottom
PC4430  SC10P50V2JN-4DLGP  [C402H22]  25.59 42.69 0 top
PC4431  SCD01U25V2KX-3DLGP  [C402H22]  27.98 39.95 0 top
PC4432  SC1KP50V2KX-1DLGP  [C402H22]  29.2 40.07 90 top
PC4433  SC1KP50V2KX-1DLGP  [C402H22]  27.6 41.5 0 top
PC4434  SC22U25V5MX-GP  [C805H58]  47.16 54.12 0 bottom
PC4435  SC1KP50V2KX-1DLGP  [C402H22]  34.58 56.41 270 top
PC4436  SCD22U25V3KX-DL-GP  [C603H36]  31.08 52.47 180 top
PC4437  SC22U25V5MX-GP  [C805H58]  47.92 40.53 270 bottom
PC4438  SCD1U16V2KX-3DLGP  [C402H22]  24.02 33.95 0 top
PC4439  SC1U25V3KX-1-DLGP  [C603H36]  33.29 46.04 270 top
PC4440  SC1U25V3KX-1-DLGP  [C603H36]  30.9 42.44 0 bottom
PC4445  SCD1U16V2KX-3DLGP  [C402H22]  28.36 41.8 270 bottom
PC4501  SCD1U25V2KX-1-DL-GP  [C402H22]  90.97 24.78 0 bottom
PC4502  SC10U25V5KX-DL-GP  [C805H58]  92.27 24.76 0 bottom
PC4503  SC10U25V5KX-DL-GP  [C805H58]  95.87 24.78 0 bottom
PC4504  SC10U25V5KX-DL-GP  [C805H58]  94.07 24.43 0 bottom
PC4505  SC10U25V5KX-DL-GP  [C805H58]  50.76 14.5 180 bottom
PC4506  SCD1U25V2KX-1-DL-GP  [C402H22]  88.94 24.15 180 bottom
PC4507  SC4D7U6D3V3KX-DLGP  [C603H36]  90.08 16.91 270 bottom
PC4508  SCD1U25V2KX-1-DL-GP  [C402H22]  91.73 16.91 180 bottom
PC4509  SC22U6D3V3MX-1-DL-GP  [C603H40]  78.53 21.74 0 bottom
PC4510  SC22U6D3V3MX-1-DL-GP  [C603H40]  78.53 16.27 180 bottom
PC4511  SC22U6D3V3MX-1-DL-GP  [C603H40]  79.8 16.27 180 bottom
PC4512  SC22U6D3V3MX-1-DL-GP  [C603H40]  79.8 21.74 0 bottom
PC4513  SCD1U25V2KX-1-DL-GP  [C402H22]  76.24 21.86 0 bottom
PC4514  SC22U6D3V3MX-1-DL-GP  [C603H40]  64.56 21.74 0 bottom
PC4515  SC22U6D3V3MX-1-DL-GP  [C603H40]  64.5 15 180 bottom
PC4516  SC22U6D3V3MX-1-DL-GP  [C603H40]  65.83 21.74 0 bottom
PC4517  SC22U6D3V3MX-1-DL-GP  [C603H40]  65.77 15 180 bottom
PC4518  SCD1U16V2KX-3DLGP  [C402H22]  68.11 14.88 180 bottom
PC4519  SC10U25V5KX-DL-GP  [C805H58]  52.57 14.88 180 bottom
PC4520  SC4D7U6D3V3KX-DLGP  [C603H36]  56.76 23.84 270 bottom
PC4521  SCD1U25V2KX-1-DL-GP  [C402H22]  55.16 15 0 bottom
PC4522  SCD1U25V2KX-1-DL-GP  [C402H22]  49.26 14.37 180 bottom
PC4523  SC10U25V5KX-DL-GP  [C805H58]  47.28 16.27 90 bottom
PC4524  SC2D2U10V3KX-1DLGP-U  [C603H36]  56.55 22.55 270 bottom
PC4525  SC22U6D3V3MX-1-DL-GP  [C603H40]  77.26 16.27 180 bottom
PC4526  SC1KP50V2KX-1DLGP  [C402H22]  53.25 22.37 0 bottom
PC4527  SC22U6D3V3MX-1-DL-GP  [C603H40]  67.1 21.74 0 bottom
PC4528  SCD1U25V2KX-1-DL-GP  [C402H22]  68.11 21.86 0 bottom
PC4529  SC22U6D3V3MX-1-DL-GP  [C603H40]  67.04 15 180 bottom
PC4530  SCD1U25V2KX-1-DL-GP  [C402H22]  50.97 22.37 0 bottom
PC4531  SCD1U25V2KX-1-DL-GP  [C402H22]  52.49 22.37 180 top
PC4532  SCD1U25V2KX-1-DL-GP  [C402H22]  91.61 16.78 0 top
PC4533  SC1KP50V2KX-1DLGP  [C402H22]  90.84 16.78 0 top
PC4542  SC22U6D3V3MX-1-DL-GP  [C603H40]  77.26 21.74 0 bottom
PC4543  SCD1U25V2KX-1-DL-GP  [C402H22]  76.24 16.4 180 bottom
PC4601  SC2200P50V2KX-2DLGP  [C402H22]  42.58 70.63 180 bottom
PC4602  SCD1U25V2KX-1-DL-GP  [C402H22]  47.26 80.96 180 bottom
PC4603  SCD1U25V2KX-1-DL-GP  [C402H22]  41.57 77.49 180 bottom
PC4604  SC330P50V2KX-3-DL-GP  [C402H22]  53.89 75.46 270 top
PC4605  SCD047U25V2KX-4-GP  [C402H22]  42.61 74.97 180 bottom
PC4606  SCD22U25V3KX-DL-GP  [C603H36]  45 77.74 90 bottom
PC4607  SC1U10V2KX-1DLGP  [C402H22]  47.38 78.54 0 bottom
PC4608  SCD022U16V2KX-3DLGP  [C402H22]  40.17 74.44 0 bottom
PC4610  SC33P50V2JN-3DLGP  [C402H22]  53.89 74.69 270 top
PC4611  SC2200P50V2KX-2DLGP  [C402H22]  44.01 75.84 270 bottom
PC4612  SC2200P50V2KX-2DLGP  [C402H22]  56.91 75.89 270 bottom
PC4613  SCD01U25V2KX-3DLGP  [C402H22]  45.51 73.93 90 top
PC4614  SC470P50V2KX-3DLGP  [C402H22]  56.91 75.11 270 bottom
PC4615  SCD01U50V2KX-1DLGP  [C402H22]  56.99 74.34 90 bottom
PC4616  SC1KP50V2KX-1DLGP  [C402H22]  43.6 73.42 0 top
PC4617  SC1KP50V2KX-1DLGP  [C402H22]  42.33 71.9 180 top
PC4618  SC470P50V2KX-3DLGP  [C402H22]  54.67 73.93 0 bottom
PC4619  SC1KP50V2KX-1DLGP  [C402H22]  54.78 72.41 180 bottom
PC4620  SCD01U50V2KX-1DLGP  [C402H22]  41.57 71.9 0 top
PC4621  SC680P50V2KX-2GP  [C402H22]  41.95 70.76 90 top
PC4622  SCD01U25V2KX-3DLGP  [C402H22]  53.25 72.28 0 bottom
PC4623  SC2200P50V2KX-2DLGP  [C402H22]  52.11 69.11 180 top
PC4624  SC33P50V2JN-3DLGP  [C402H22]  43.85 70.25 90 bottom
PC4625  SCD022U16V2KX-3DLGP  [C402H22]  52.49 68.47 270 bottom
PC4626  SCD022U16V2KX-3DLGP  [C402H22]  54.65 66.82 0 bottom
PC4628  SCD022U16V2KX-3DLGP  [C402H22]  54.4 70.38 180 bottom
PC4629  SC330P50V2KX-3-DL-GP  [C402H22]  45.89 72.03 270 top
PC4630  SCD047U25V2KX-4-GP  [C402H22]  52.11 70.63 180 bottom
PC4631  SCD1U25V2KX-1-DL-GP  [C402H22]  41.82 69.11 0 bottom
PC4632  SC2200P50V2KX-2DLGP  [C402H22]  44.36 69.11 0 bottom
PC4633  SCD1U25V2KX-1-DL-GP  [C402H22]  50.97 67.07 270 top
PC4634  SCD047U25V2KX-4-GP  [C402H22]  42.71 67.23 270 bottom
PC4635  SCD01U25V2KX-3DLGP  [C402H22]  44.18 65.45 270 bottom
PC4637  SCD01U25V2KX-3DLGP  [C402H22]  45.89 67.71 270 bottom
PC4638  SC330P50V2KX-3-DL-GP  [C402H22]  50.76 67.43 180 bottom
PC4639  SC33P50V2JN-3DLGP  [C402H22]  48.43 67.33 0 top
PC4640  SC2200P50V2KX-2DLGP  [C402H22]  49.19 65.68 0 top
PC4641  SC330P50V2KX-3-DL-GP  [C402H22]  48.55 65.55 180 bottom
PC4642  SC1KP50V2KX-1DLGP  [C402H22]  45.76 66.19 270 bottom
PC4643  SC1KP50V2KX-1DLGP  [C402H22]  47.41 65.93 90 bottom
PC4644  SCD01U50V2KX-1DLGP  [C402H22]  47.41 65.17 270 bottom
PC4651  SC1KP50V2KX-1DLGP  [C402H22]  56.71 76.65 270 bottom
PC4652  SCD022U16V2KX-3DLGP  [C402H22]  44.18 66.21 270 bottom
PC4653  SCD047U25V2KX-4-GP  [C402H22]  53.63 70.63 180 bottom
PC4654  SCD01U25V2KX-3DLGP  [C402H22]  55.16 70.38 180 bottom
PC4701  SC10U25V3MX-GP  [C603H40]  64.89 71.14 270 bottom
PC4702  SC10U25V3MX-GP  [C603H40]  64.89 71.14 90 top
PC4703  SC10U25V3MX-GP  [C603H40]  64.63 72.41 270 bottom
PC4704  SC10U25V3MX-GP  [C603H40]  64.63 72.41 90 top
PC4706  SC1KP50V2KX-1DLGP  [C402H22]  66.84 69.36 180 top
PC4707  SCD22U25V3KX-DL-GP  [C603H36]  59.2 69.87 270 bottom
PC4708  SC1U10V2KX-1DLGP  [C402H22]  59.48 66.82 90 bottom
PC4766  SC1U10V2KX-1DLGP  [C402H22]  63.89 64.28 270 bottom
PC4802  SC10U25V3MX-GP  [C603H40]  64 93.62 90 top
PC4803  SC10U25V3MX-GP  [C603H40]  63.74 92.32 90 top
PC4804  SC10U25V3MX-GP  [C603H40]  64 93.62 270 bottom
PC4805  SC10U25V3MX-GP  [C603H40]  63.74 92.32 270 bottom
PC4808  SCD22U25V3KX-DL-GP  [C603H36]  58.89 90.85 270 bottom
PC4809  SC1U10V2KX-1DLGP  [C402H22]  59.09 87.78 90 bottom
PC4810  SC1KP50V2KX-1DLGP  [C402H22]  67.1 90.44 180 top
PC4811  SCD22U25V3KX-DL-GP  [C603H36]  58.97 79.65 270 bottom
PC4812  SC1U10V2KX-1DLGP  [C402H22]  59.48 76.6 90 bottom
PC4813  SC1KP50V2KX-1DLGP  [C402H22]  66.97 79.65 180 top
PC4814  SC10U25V3MX-GP  [C603H40]  63.69 83.08 90 top
PC4815  SC10U25V3MX-GP  [C603H40]  64.05 81.81 90 top
PC4816  SC10U25V3MX-GP  [C603H40]  63.69 83.08 270 bottom
PC4817  SC10U25V3MX-GP  [C603H40]  64.05 81.81 270 bottom
PC4866  SC1U10V2KX-1DLGP  [C402H22]  63.67 74.31 90 top
PC4877  SC1U10V2KX-1DLGP  [C402H22]  63.67 84.6 90 top
PC5001  SC2D2U10V3KX-1DLGP-U  [C603H36]  170.04 98.11 270 top
PC5002  SC10U25V5KX-DL-GP  [C805H58]  167.68 103.27 0 bottom
PC5003  SC10U25V5KX-DL-GP  [C805H58]  168.64 100.31 180 bottom
PC5004  SCD1U25V2KX-1-DL-GP  [C402H22]  167.25 100.48 180 bottom
PC5005  SCD22U25V3KX-DL-GP  [C603H36]  173.14 104.16 90 bottom
PC5104  SC22U6D3V3MX-1-DL-GP  [C603H40]  68.11 61.74 0 bottom
PC5105  SC22U6D3V3MX-1-DL-GP  [C603H40]  67.22 56.53 180 bottom
PC5107  SC22U6D3V3MX-1-DL-GP  [C603H40]  65.95 56.53 180 bottom
PC5108  SC1U10V2KX-1DLGP  [C402H22]  52.74 62.12 90 bottom
PC5109  SC22U6D3V3MX-1-DL-GP  [C603H40]  66.84 61.74 0 bottom
PC5111  SC10U25V5KX-DL-GP  [C805H58]  59.02 54.96 270 bottom
PC5112  SC4D7U6D3V3KX-L-GP  [C603H36]  50.59 63.9 90 bottom
PC5113  SCD1U25V2KX-1-DL-GP  [C402H22]  52.69 56.36 180 bottom
PC5114  SCD1U25V2KX-1-DL-GP  [C402H22]  57.06 55.01 180 bottom
PC5115  SC10U25V5KX-DL-GP  [C805H58]  58.61 53.1 270 bottom
PC5116  SCD1U25V2KX-1-DL-GP  [C402H22]  59.07 56.25 270 bottom
PC5117  SC10U6D3V3MX-L-GP  [C603H38]  50.08 49.55 270 top
PC5118  SC1500P50V2KX-2GP  [C402H22]  60.87 61.11 180 top
PC5122  SC1U10V2KX-1DLGP  [C402H22]  57.06 55.26 0 top
PC5124  SC10U6D3V3MX-DL-GP  [C603H36]  52.49 49.93 90 top
PC5201  SC22U6D3V3MX-1-DL-GP  [C603H40]  169.33 80.03 180 bottom
PC5202  SC1U10V2KX-1DLGP  [C402H22]  176.52 73.58 270 bottom
PC5203  SC22U6D3V3MX-1-DL-GP  [C603H40]  168.06 80.03 180 bottom
PC5204  SCD1U25V2KX-1-DL-GP  [C402H22]  175.93 74.74 0 bottom
PC5205  SC22U6D3V3MX-1-DL-GP  [C603H40]  170.6 80.03 180 bottom
PC5206  SC22U6D3V3MX-1-DL-GP  [C603H40]  171.87 80.03 180 bottom
PC5208  SCD1U25V2KX-1-DL-GP  [C402H22]  179.03 85.72 270 bottom
PC5209  SC10U25V5KX-DL-GP  [C805H58]  165.16 74.77 0 bottom
PC5210  SC10U25V5KX-DL-GP  [C805H58]  168.82 74.57 0 bottom
PC5211  SC10U25V5KX-DL-GP  [C805H58]  166.99 74.21 0 bottom
PC5212  SC220P50V2KX-3DLGP  [C402H22]  173.78 69.92 180 bottom
PC5213  SCD01U25V2KX-3DLGP  [C402H22]  176.52 72.81 270 bottom
PC5214  SCD1U25V2KX-1-DL-GP  [C402H22]  169.08 71.27 180 bottom
PC5215  SCD1U16V2KX-3DLGP  [C402H22]  176.57 70.43 270 bottom
PC5216  SC10U25V5KX-DL-GP  [C805H58]  167.53 71.27 180 bottom
PC5401  SC1U10V2KX-1DLGP  [C402H22]  171.87 2.3 90 top
PC5402  SC10U6D3V3MX-DL-GP  [C603H36]  170.98 11.19 0 bottom
PC5403  SC10U6D3V3MX-DL-GP  [C603H36]  173.52 4.34 0 bottom
PC5404  SC22U6D3V3MX-1-DL-GP  [C603H40]  172.25 11.45 0 bottom
PC5405  SC68P50V2JN-1DLGP  [C402H22]  169.46 9.54 90 bottom
PC5406  SC4700P50V2KX-1GP  [C402H22]  168.19 2.81 180 top
PC5410  SC1U25V3KX-1-DLGP  [C603H36]  110.91 24.28 180 bottom
PC5411  SC68P50V2JN-1DLGP  [C402H22]  119.47 25.95 0 bottom
PC5412  SC22U6D3V3MX-1-DL-GP  [C603H40]  119.04 23.01 180 bottom
PC5413  SC10U6D3V3MX-DL-GP  [C603H36]  121.37 25.88 0 bottom
PC5414  SC10U6D3V3MX-DL-GP  [C603H36]  116.52 22.19 270 bottom
PC5427  SCD1U25V2KX-1-DL-GP  [C402H22]  110.4 26.43 90 bottom
PD4401  BAT54C-12-GP  [SOT-23-9H44]  22.39 53.1 0 bottom
PD4404  L1SS355T1G-GP  [SOD323AKH44]  35.85 38.14 180 bottom
PD4407  RB751V-40H-GP  [SOD323AKH38]  37.5 40.79 90 bottom
PD4408  BAT54C-12-GP  [SOT-23-9H44]  22.42 49.93 0 bottom
PD5101  AZ4024-01L-R7G-GP  [SOD323AKH40]  51.35 53.49 0 bottom
PG4401  GAP-CLOSE-PWR-3-GP  [GAP-CLOSE-PWR-3]  40.43 60.72 180 bottom
PG4402  GAP-CLOSE-PWR-3-GP  [GAP-CLOSE-PWR-3]  40.43 59.71 180 bottom
PG4405  GAP-CLOSE-PWR-3-GP  [GAP-CLOSE-PWR-3]  102.27 18.18 0 bottom
PG4406  GAP-CLOSE-PWR-3-GP  [GAP-CLOSE-PWR-3]  102.27 16.66 0 bottom
PG4408  GAP-CLOSE-PWR-3-GP  [GAP-CLOSE-PWR-3]  22.16 43.35 180 top
PG4501  GAP-CLOSE-PWR-3-GP  [GAP-CLOSE-PWR-3]  44.87 23.01 270 top
PG4502  GAP-CLOSE-PWR-3-GP  [GAP-CLOSE-PWR-3]  45.63 23.01 270 top
PG4503  GAP-CLOSE-PWR-3-GP  [GAP-CLOSE-PWR-3]  48.68 23.01 270 top
PG4504  GAP-CLOSE-PWR-3-GP  [GAP-CLOSE-PWR-3]  47.92 23.01 270 top
PG4505  GAP-CLOSE-PWR-3-GP  [GAP-CLOSE-PWR-3]  46.39 23.01 270 top
PG4506  GAP-CLOSE-PWR-3-GP  [GAP-CLOSE-PWR-3]  47.16 23.01 270 top
PG4507  GAP-CLOSE-PWR-3-GP  [GAP-CLOSE-PWR-3]  75.1 19.96 180 bottom
PG4508  GAP-CLOSE-PWR-3-GP  [GAP-CLOSE-PWR-3]  75.1 20.72 180 bottom
PG4509  GAP-CLOSE-PWR-3-GP  [GAP-CLOSE-PWR-3]  75.1 21.48 180 bottom
PG4510  GAP-CLOSE-PWR-3-GP  [GAP-CLOSE-PWR-3]  69.25 19.83 0 bottom
PG4511  GAP-CLOSE-PWR-3-GP  [GAP-CLOSE-PWR-3]  69.25 19.07 0 bottom
PG4512  GAP-CLOSE-PWR-3-GP  [GAP-CLOSE-PWR-3]  69.25 18.31 0 bottom
PG4513  GAP-CLOSE-PWR-3-GP  [GAP-CLOSE-PWR-3]  69.25 15.26 0 bottom
PG4515  GAP-CLOSE-PWR-3-GP  [GAP-CLOSE-PWR-3]  97.5 24.15 180 bottom
PG4516  GAP-CLOSE-PWR-3-GP  [GAP-CLOSE-PWR-3]  97.5 21.86 180 bottom
PG4517  GAP-CLOSE-PWR-3-GP  [GAP-CLOSE-PWR-3]  97.5 22.62 180 bottom
PG4518  GAP-CLOSE-PWR-3-GP  [GAP-CLOSE-PWR-3]  97.5 23.39 180 bottom
PG4519  GAP-CLOSE-PWR-3-GP  [GAP-CLOSE-PWR-3]  89.73 15.82 0 bottom
PG4520  GAP-CLOSE-PWR-3-GP  [GAP-CLOSE-PWR-3]  75.1 18.43 180 bottom
PG4521  GAP-CLOSE-PWR-3-GP  [GAP-CLOSE-PWR-3]  75.1 19.2 180 bottom
PG4522  GAP-CLOSE-PWR-3-GP  [GAP-CLOSE-PWR-3]  69.25 20.59 0 bottom
PG4523  GAP-CLOSE-PWR-3-GP  [GAP-CLOSE-PWR-3]  69.25 17.54 0 bottom
PG4524  GAP-CLOSE-PWR-3-GP  [GAP-CLOSE-PWR-3]  69.25 16.78 0 bottom
PG4525  GAP-CLOSE-PWR-3-GP  [GAP-CLOSE-PWR-3]  69.25 16.02 0 bottom
PG4526  GAP-CLOSE-PWR-3-GP  [GAP-CLOSE-PWR-3]  75.1 17.67 180 bottom
PG4527  GAP-CLOSE-PWR-3-GP  [GAP-CLOSE-PWR-3]  69 21.86 270 bottom
PG4528  GAP-CLOSE-PWR-3-GP  [GAP-CLOSE-PWR-3]  53.58 24.68 180 bottom
PG4529  GAP-CLOSE-PWR-3-GP  [GAP-CLOSE-PWR-3]  48.93 19.45 0 bottom
PG4530  GAP-CLOSE-PWR-3-GP  [GAP-CLOSE-PWR-3]  75.35 16.4 90 bottom
PG4531  GAP-CLOSE-PWR-3-GP  [GAP-CLOSE-PWR-3]  95.04 17.67 90 top
PG4707  GAP-CLOSE-PWR-3-GP  [GAP-CLOSE-PWR-3]  70.52 67.84 180 bottom
PG4708  GAP-CLOSE-PWR-3-GP  [GAP-CLOSE-PWR-3]  72.43 67.84 0 bottom
PG4709  GAP-CLOSE-PWR-3-GP  [GAP-CLOSE-PWR-3]  61.13 73.3 0 bottom
PG4710  GAP-CLOSE-PWR-3-GP  [GAP-CLOSE-PWR-3]  61.13 72.54 0 bottom
PG4711  GAP-CLOSE-PWR-3-GP  [GAP-CLOSE-PWR-3]  61.13 71.77 0 bottom
PG4712  GAP-CLOSE-PWR-3-GP  [GAP-CLOSE-PWR-3]  61.13 71.01 0 bottom
PG4713  GAP-CLOSE-PWR-3-GP  [GAP-CLOSE-PWR-3]  61.89 71.01 0 top
PG4808  GAP-CLOSE-PWR-3-GP  [GAP-CLOSE-PWR-3]  70.52 88.41 180 bottom
PG4809  GAP-CLOSE-PWR-3-GP  [GAP-CLOSE-PWR-3]  72.56 88.41 0 bottom
PG4813  GAP-CLOSE-PWR-3-GP  [GAP-CLOSE-PWR-3]  70.4 78 180 bottom
PG4815  GAP-CLOSE-PWR-3-GP  [GAP-CLOSE-PWR-3]  72.43 78 0 bottom
PG4816  GAP-CLOSE-PWR-3-GP  [GAP-CLOSE-PWR-3]  59.86 95.27 0 bottom
PG4817  GAP-CLOSE-PWR-3-GP  [GAP-CLOSE-PWR-3]  60.75 81.3 0 top
PG4818  GAP-CLOSE-PWR-3-GP  [GAP-CLOSE-PWR-3]  60.75 82.06 0 top
PG4819  GAP-CLOSE-PWR-3-GP  [GAP-CLOSE-PWR-3]  60.75 82.82 0 top
PG4820  GAP-CLOSE-PWR-3-GP  [GAP-CLOSE-PWR-3]  60.75 83.58 0 top
PG4821  GAP-CLOSE-PWR-3-GP  [GAP-CLOSE-PWR-3]  60.75 84.35 0 top
PG4822  GAP-CLOSE-PWR-3-GP  [GAP-CLOSE-PWR-3]  59.86 94.51 0 bottom
PG4823  GAP-CLOSE-PWR-3-GP  [GAP-CLOSE-PWR-3]  59.86 97.55 0 bottom
PG4824  GAP-CLOSE-PWR-3-GP  [GAP-CLOSE-PWR-3]  59.86 96.79 0 bottom
PG4825  GAP-CLOSE-PWR-3-GP  [GAP-CLOSE-PWR-3]  59.86 96.03 0 bottom
PG5001  GAP-CLOSE-PWR-3-GP  [GAP-CLOSE-PWR-3]  157.27 101.2 180 bottom
PG5002  GAP-CLOSE-PWR-3-GP  [GAP-CLOSE-PWR-3]  169.84 103.02 90 bottom
PG5003  GAP-CLOSE-PWR-3-GP  [GAP-CLOSE-PWR-3]  169.08 103.02 90 bottom
PG5011  GAP-CLOSE-PWR-3-GP  [GAP-CLOSE-PWR-3]  159.55 101.2 0 bottom
PG5101  GAP-CLOSE-PWR-3-GP  [GAP-CLOSE-PWR-3]  49.7 53.23 0 bottom
PG5102  GAP-CLOSE-PWR-3-GP  [GAP-CLOSE-PWR-3]  49.7 53.99 0 bottom
PG5103  GAP-CLOSE-PWR-3-GP  [GAP-CLOSE-PWR-3]  49.7 54.76 0 bottom
PG5110  GAP-CLOSE-PWR-3-GP  [GAP-CLOSE-PWR-3]  58.33 56.53 180 top
PG5113  GAP-CLOSE-PWR-3-GP  [GAP-CLOSE-PWR-3]  64.81 57.17 90 bottom
PG5114  GAP-CLOSE-PWR-3-GP  [GAP-CLOSE-PWR-3]  50.97 62.12 0 bottom
PG5116  GAP-CLOSE-PWR-3-GP  [GAP-CLOSE-PWR-3]  58.33 55.77 180 top
PG5122  GAP-CLOSE-PWR-3-GP  [GAP-CLOSE-PWR-3]  48.81 58.82 90 bottom
PG5201  GAP-CLOSE-PWR-3-GP  [GAP-CLOSE-PWR-3]  166.64 86.89 180 bottom
PG5202  GAP-CLOSE-PWR-3-GP  [GAP-CLOSE-PWR-3]  166.64 87.65 180 bottom
PG5203  GAP-CLOSE-PWR-3-GP  [GAP-CLOSE-PWR-3]  166.64 86.12 180 bottom
PG5204  GAP-CLOSE-PWR-3-GP  [GAP-CLOSE-PWR-3]  166.64 85.36 180 bottom
PG5205  GAP-CLOSE-PWR-3-GP  [GAP-CLOSE-PWR-3]  166.64 84.6 180 bottom
PG5206  GAP-CLOSE-PWR-3-GP  [GAP-CLOSE-PWR-3]  166.64 83.84 180 bottom
PG5207  GAP-CLOSE-PWR-3-GP  [GAP-CLOSE-PWR-3]  166.64 83.08 180 bottom
PG5208  GAP-CLOSE-PWR-3-GP  [GAP-CLOSE-PWR-3]  166.64 82.31 180 bottom
PG5209  GAP-CLOSE-PWR-3-GP  [GAP-CLOSE-PWR-3]  166.64 81.55 180 bottom
PG5210  GAP-CLOSE-PWR-3-GP  [GAP-CLOSE-PWR-3]  165.39 71.01 90 bottom
PG5211  GAP-CLOSE-PWR-3-GP  [GAP-CLOSE-PWR-3]  166.64 80.79 180 bottom
PG5212  GAP-CLOSE-PWR-3-GP  [GAP-CLOSE-PWR-3]  164.63 71.01 90 bottom
PG5214  GAP-CLOSE-PWR-3-GP  [GAP-CLOSE-PWR-3]  166.16 71.01 90 bottom
PG5223  GAP-CLOSE-PWR-6-GP  [GAP-CLOSE-PWR]  179.11 84.85 180 bottom
PG5401  GAP-CLOSE-PWR-3-GP  [GAP-CLOSE-PWR-3]  123.23 25.16 0 bottom
PG5402  GAP-CLOSE-PWR-3-GP  [GAP-CLOSE-PWR-3]  123.23 25.93 0 bottom
PG5403  GAP-CLOSE-PWR-3-GP  [GAP-CLOSE-PWR-3]  173.01 8.91 0 bottom
PG5404  GAP-CLOSE-PWR-3-GP  [GAP-CLOSE-PWR-3]  173.01 9.67 0 bottom
PL4401  IND-2D2UH-447-GP  [L109100-2430-UH119]  39.41 49.42 180 bottom
PL4501  IND-1D5UH-23-GP-U  [L7066-1830-UH119]  84.62 19.7 90 bottom
PL4502  IND-1D5UH-23-GP-U  [L7066-1830-UH119]  59.75 18.33 90 bottom
PL4701  COIL-D15UH-8-GP  [L7366-1930H95]  71.51 67.84 270 bottom
PL4801  COIL-D15UH-8-GP  [L7366-1930H95]  71.54 88.41 270 bottom
PL4802  COIL-D15UH-8-GP  [L7366-1930H95]  71.41 78 270 bottom
PL5001  IND-D47UH-22-GP-U  [L7066-1830-UH119]  158.41 101.33 90 bottom
PL5101  COIL-1UH-73-GP  [L4947-1115H119]  61.13 59.58 270 bottom
PL5201  COIL-1UH-57-GP  [L7066-1830-UH95]  176.06 80.23 0 bottom
PQ4405  2N7002KDW-1-GP  [SOT-363H44]  26.73 34.92 90 top
PQ4408  MMBT3906-3-GP  [SOT23CBE2D4H44]  33.31 38.27 270 bottom
PQ4415  2N7002KDW-1-GP  [SOT-363H44]  23.15 43.33 0 bottom
PQ4416  2N7002KDW-1-GP  [SOT-363H44]  23.41 38.88 180 top
PQ4417  2N7002K-2-GP  [SOT23DGS2D4H44]  19.47 39.39 270 top
PQ4418  2N7002KDW-1-GP  [SOT-363H44]  28.36 39.77 180 bottom
PR2455  150KR2F-L-GP  [R402H16]  27.22 24.28 270 top
PR4401  D02R6F-GP  [R1206H24]  42.2 60.22 180 bottom
PR4402  2D2R3-1-U-GP  [R603H22]  29.68 52.47 0 top
PR4403  2D2R5J-1-GP  [R805H24]  21.76 50.95 270 top
PR4404  402KR2F-GP  [R402H16]  24.04 47.64 270 bottom
PR4405  4D7R2F-GP  [R402H16]  33.16 51.1 90 top
PR4406  100KR2F-L1-GP  [R402H16]  26.46 47.52 270 bottom
PR4407  D01R3721F-GP-U  [R3720H40]  99.99 17.42 180 bottom
PR4408  2D2R3-1-U-GP  [R603H22]  33.29 47.44 270 top
PR4409  100KR2F-L1-GP  [R402H16]  24.8 42.69 0 top
PR4410  105KR2F-1-GP  [R402H16]  26.43 42.39 180 top
PR4411  499R2F-2-GP  [R402H16]  28.36 42.56 0 top
PR4412  0R0402-PAD-2-GP  [0R0402-PAD-1]  29.22 39.31 90 top
PR4413  6K04R2F-GP  [R402H16]  29.5 41.29 0 top
PR4414  -  [0R0805-PAD]  43.85 53.26 0 top
PR4416  2D2R5J-1-GP  [R805H24]  37.66 56.46 270 top
PR4417  100KR2F-L1-GP  [R402H16]  21.5 47.49 90 top
PR4420  -  [0R0805-PAD]  38.95 42.36 270 top
PR4422  1R2F-GP  [R402H16]  26.18 52.98 0 top
PR4423  1R2F-GP  [R402H16]  26.94 52.98 0 top
PR4424  1R2F-GP  [R402H16]  32.3 42.49 180 top
PR4425  1R2F-GP  [R402H16]  31.54 42.49 180 top
PR4426  196KR2F-GP  [R402H16]  23.66 44.34 270 top
PR4427  100KR2F-L1-GP  [R402H16]  21.78 48.25 270 top
PR4429  100KR2F-L1-GP  [R402H16]  23.28 43.07 180 top
PR4435  100KR2F-L1-GP  [R402H16]  20.99 44.85 0 top
PR4436  1MR2J-1-GP  [R402H16]  22.37 47.14 90 bottom
PR4450  10KR2F-2-GP  [R402H16]  23.23 34.1 180 top
PR4462  0R0402-PAD-2-GP  [0R0402-PAD-1]  28.36 36.72 180 top
PR4463  0R2J-2-GP  [R402H16]  24.04 43.07 180 top
PR4472  100KR2F-L1-GP  [R402H16]  23.53 36.21 180 top
PR4473  100KR2J-1-GP  [R402H16]  21.88 47.9 270 bottom
PR4474  100KR2F-L1-GP  [R402H16]  24.3 36.21 0 top
PR4475  680KR2F-GP  [R402H16]  29.25 36.72 0 top
PR4476  0R0402-PAD-2-GP  [0R0402-PAD-1]  27.01 36.57 270 top
PR4477  0R0402-PAD-2-GP  [0R0402-PAD-1]  37.63 39.39 90 bottom
PR4478  100R2F-L1-GP-U  [R402H14]  31.92 42.69 180 bottom
PR4479  100KR2J-1-GP  [R402H16]  20.77 38.04 180 top
PR4483  0R0402-PAD-2-GP  [0R0402-PAD-1]  21.53 39.59 180 top
PR4484  0R2J-2-GP  [R402H16]  26.2 40.02 0 bottom
PR4485  0R0402-PAD-2-GP  [0R0402-PAD-1]  25.82 38.32 0 top
PR4486  10KR2F-2-GP  [R402H16]  28.72 43.05 0 bottom
PR4487  100KR2F-L1-GP  [R402H16]  27.47 42.56 270 bottom
PR4488  0R0402-PAD-2-GP  [0R0402-PAD-1]  17.31 41.8 180 top
PR4489  0R0402-PAD-2-GP  [0R0402-PAD-1]  25.06 38.32 0 top
PR4490  0R0402-PAD-2-GP  [0R0402-PAD-1]  23.71 46.47 270 top
PR4491  0R0402-PAD-2-GP  [0R0402-PAD-1]  23.71 45.71 270 top
PR4492  0R0402-PAD-2-GP  [0R0402-PAD-1]  23.74 41.5 270 bottom
PR4493  0R0402-PAD-2-GP  [0R0402-PAD-1]  20.59 43.05 180 top
PR4494  0R0402-PAD-2-GP  [0R0402-PAD-1]  25.85 40.61 45 top
PR4495  0R2J-2-GP  [R402H16]  32.93 40.91 0 bottom
PR4501  0R0603-PAD-2-GP-U  [0R0603-PAD-1-U]  89.96 24.99 0 bottom
PR4502  0R0603-PAD-2-GP-U  [0R0603-PAD-1-U]  54.12 13.81 180 bottom
PR4503  0R2J-2-GP  [R402H16]  91.86 12.85 0 top
PR4504  0R0402-PAD-2-GP  [0R0402-PAD-1]  51.22 21.99 90 top
PR4505  100KR2J-1-GP  [R402H16]  92.75 19.7 0 top
PR4506  1KR2F-3-GP  [R402H16]  90.08 16.78 0 top
PR4507  1KR2F-3-GP  [R402H16]  54.01 22.37 180 bottom
PR4508  200KR2F-L1-GP  [R402H16]  92.5 16.91 180 bottom
PR4509  1KR2F-3-GP  [R402H16]  93.26 16.91 0 bottom
PR4510  100KR2J-1-GP  [R402H16]  50.08 19.83 0 bottom
PR4511  1KR2F-3-GP  [R402H16]  50.2 22.37 180 bottom
PR4512  200KR2F-L1-GP  [R402H16]  51.73 22.37 0 bottom
PR4513  1MR2J-1-GP  [R402H16]  53.25 22.37 180 top
PR4514  1MR2J-1-GP  [R402H16]  92.37 16.78 0 top
PR4515  0R0402-PAD-2-GP  [0R0402-PAD-1]  93.18 12.16 270 top
PR4516  0R0402-PAD-2-GP  [0R0402-PAD-1]  93.13 16.78 180 top
PR4530  0R2J-2-GP  [R402H16]  91.1 12.85 180 top
PR4551  560KR2F-GP  [R402H16]  52.49 22.37 0 bottom
PR4601  0R0402-PAD-1-GP  [0R0402-PAD]  42.33 73.04 270 top
PR4602  0R0402-PAD-1-GP  [0R0402-PAD]  42.33 73.81 270 top
PR4603  1KR2F-3-GP  [R402H16]  50.43 81.08 180 bottom
PR4604  100R2F-L1-GP-U  [R402H14]  48.15 81.08 180 bottom
PR4605  75R2F-2-GP  [R402H16]  48.91 81.08 180 bottom
PR4606  45D3R2F-L-GP  [R402H16]  49.67 81.08 180 bottom
PR4607  100R2F-L1-GP-U  [R402H14]  50.48 78.67 180 bottom
PR4608  100KR2F-L1-GP  [R402H16]  53.89 76.22 270 top
PR4609  10KR2F-L1-GP  [R402H15]  51.5 78.73 180 bottom
PR4610  1R2F-GP  [R402H16]  46.62 78.54 180 bottom
PR4611  NTC-10K-29-GP-U  [NTC-402H22-U]  160.67 96.97 90 bottom
PR4612  0R0402-PAD-1-GP  [0R0402-PAD]  45.63 80.49 180 bottom
PR4613  0R0402-PAD-2-GP  [0R0402-PAD-1]  40.55 75.58 90 bottom
PR4614  0R2J-2-GP  [R402H16]  53.35 77.91 0 bottom
PR4615  1KR2F-3-GP  [R402H16]  41.31 76.35 270 bottom
PR4616  11KR2F-L-GP  [R402H16]  53.73 76.64 270 bottom
PR4617  NTC-470K-17-GP  [NTC-402H22-U]  62.07 85.26 90 bottom
PR4618  11KR2F-L-GP  [R402H16]  41.82 75.08 0 bottom
PR4620  430R2F-GP  [R402H16]  42.97 77.11 270 bottom
